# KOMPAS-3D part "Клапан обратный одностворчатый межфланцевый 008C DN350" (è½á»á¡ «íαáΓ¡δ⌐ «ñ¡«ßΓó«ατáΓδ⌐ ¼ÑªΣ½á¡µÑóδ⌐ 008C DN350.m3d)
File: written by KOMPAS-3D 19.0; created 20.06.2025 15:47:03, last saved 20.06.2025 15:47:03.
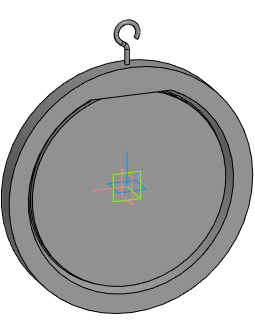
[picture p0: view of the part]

Document properties: Полное имя файла: E:\Dendor Работа Сачек\3D для проектировщиков\5.1 Тип 008C. Клапан обратный одностворчатый межфланцевый\stp_Клапан обратный одностворчатый межфланцевый 008C\Клапан обратный одностворчатый межфланцевый 008C DN350.m3d

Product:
- Part/product: Клапан обратный одностворчатый межфланцевый 008C DN350

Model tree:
1. Операция без истории:1  (labels: Клапан обратный одностворчатый межфланцевый 008C DN350)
